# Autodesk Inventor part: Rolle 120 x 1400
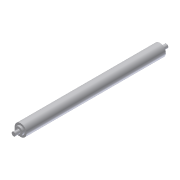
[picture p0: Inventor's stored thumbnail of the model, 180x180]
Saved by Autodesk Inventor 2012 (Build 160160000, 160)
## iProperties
Created: 2004-04
Part Number: Rolle 120 x 1400
Document SubType Name: Modeling
Manufacturer: Standard
Standards Organization: Custom
Description: Welle
Density: 1 g/cm^3
Material: Standard
Company: CAD-Verlag
+MSCProtocol1+ProtocolID: P00061127083254156
+MSCProtocol2+Protocol: P00061127083254156<@PID>[Version]<@EL>Version=2.0<@EL>[Mechsoft]<@EL>Dynamic=1<@EL>[Synchronize]<@EL>ChangedVars=<@EL>[Debug]<@EL>ChangedVars=<@EL>[Files]<@EL>D
Author: Jürgen Kronas
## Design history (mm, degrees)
sketch "Skizze2"
  geometry: L1 (0, 0)-(1535, 0) reference; L2 (0, 0)-(0, 20); L3 (0, 20)-(50, 20); L4 (50, 20)-(50, 40); L5 (50, 40)-(70, 40); L6 (70, 40)-(70, 60); L7 (1470, 60)-(1470, 40); L8 (70, 60)-(1470, 60); L9 (1485, 40)-(1485, 20); L10 (1470, 40)-(1485, 40); L11 (1535, 20)-(1535, 0); L12 (1485, 20)-(1535, 20)
  constraints: 24 end point, 6 vertical, 2 horizontal
  dimensions: "d0" = 40 diameter of L3 L1 (derived); "d1" = 80 diameter of L5 L1 (derived); "d2" = 120 diameter of L8 L1 (derived); "d3" = 80 diameter of L10 L1 (derived); "d4" = 40 diameter of L12 L1 (derived)
revolve "Drehung1" sketch "Skizze2" stored, may be unused: angle "d5" = 0 deg
feature "Keyway1"
feature "RRGroove1"
node "Volumenkörper1"
node "Volumenkörpern"
node "Oberflächenkörpern"
